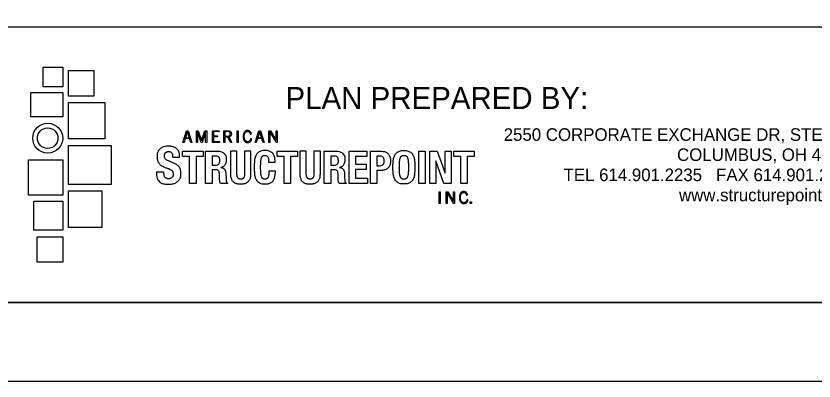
# Model space of a CAD drawing. Extents: x 10.6 to 44.6, y -2.6 to 23.4.
# Drawn here: x 13.5 to 18.57, y 1.43 to 3.75 of the extents above; entities that cross this region are included whole.
import ezdxf

# ---------------------------------------------------------------- set-up
doc = ezdxf.new("R2010")
doc.units = 0
for name, color, linetype in [('SH_Border', 7, 'Continuous'), ('SH_Cut_Line', 7, 'Continuous'), ('SH_Data', 7, 'Continuous')]:
    doc.layers.add(name, color=color, linetype=linetype)

msp = doc.modelspace()

# ---------------------------------------------------------------- linework, layer by layer
at = {"layer": 'SH_Border'}
msp.add_lwpolyline([(12.6028, 22.9265), (44.1028, 22.9265), (44.1028, 1.9265), (12.6028, 1.9265)], close=True, dxfattribs=at)
at = {"layer": 'SH_Cut_Line'}
msp.add_lwpolyline([(10.6028, 1.4265), (44.6028, 1.4265), (44.6028, 23.4265), (10.6028, 23.4265)], close=True, dxfattribs=at)
at = {"layer": 'SH_Data'}
for points in [[(13.2278, 1.9265), (19.2278, 1.9265), (19.2278, 3.6765), (13.2278, 3.6765)], [(13.6718, 3.4231), (13.7965, 3.4231), (13.7965, 3.2984), (13.6718, 3.2984)], [(13.8329, 3.4009), (13.995, 3.4009), (13.995, 3.2388), (13.8329, 3.2388)], [(13.5937, 3.2607), (13.7965, 3.2607), (13.7965, 3.1078), (13.5937, 3.1078)], [(13.8329, 3.1981), (14.0649, 3.1981), (14.0649, 2.9661), (13.8329, 2.9661)], [(13.8329, 2.9255), (14.1051, 2.9255), (14.1051, 2.676), (13.8329, 2.676)], [(13.579, 2.8342), (13.7965, 2.8342), (13.7965, 2.6096), (13.579, 2.6096)], [(13.8329, 2.6354), (14.0455, 2.6354), (14.0455, 2.4034), (13.8329, 2.4034)], [(13.6124, 2.5698), (13.7965, 2.5698), (13.7965, 2.3858), (13.6124, 2.3858)], [(13.6344, 2.3446), (13.7965, 2.3446), (13.7965, 2.1825), (13.6344, 2.1825)]]:
    msp.add_lwpolyline(points, close=True, dxfattribs=at)
for points in [[(14.5604, 2.9443), (14.5842, 3.0187), (14.5946, 3.0187), (14.6181, 2.9443), (14.6109, 2.9443), (14.6034, 2.9686), (14.5753, 2.9686), (14.5676, 2.9443), (14.5604, 2.9443)], [(14.577, 2.9742), (14.6019, 2.9742), (14.5895, 3.0131), (14.5893, 3.0131), (14.577, 2.9742)], [(14.6465, 2.9443), (14.6465, 3.0187), (14.6585, 3.0187), (14.6791, 2.9556), (14.6793, 2.9556), (14.6999, 3.0187), (14.7119, 3.0187), (14.7119, 2.9443), (14.7051, 2.9443), (14.7051, 3.0131), (14.7049, 3.0131), (14.6825, 2.9443), (14.676, 2.9443), (14.6536, 3.0131), (14.6533, 3.0131), (14.6533, 2.9443), (14.6465, 2.9443)], [(14.7478, 2.9443), (14.7478, 3.0187), (14.7903, 3.0187), (14.7903, 3.0131), (14.7546, 3.0131), (14.7546, 2.9858), (14.7803, 2.9858), (14.7803, 2.9802), (14.7546, 2.9802), (14.7546, 2.9499), (14.7923, 2.9499), (14.7923, 2.9443), (14.7478, 2.9443)], [(14.8532, 2.9795), (14.8715, 2.9443), (14.864, 2.9443), (14.8467, 2.9783), (14.8274, 2.9783), (14.8274, 2.9443), (14.8206, 2.9443), (14.8206, 3.0187), (14.8458, 3.0187)], [(14.8274, 3.0131), (14.8274, 2.9839), (14.8458, 2.9839)], [(14.8458, 3.0131), (14.8274, 3.0131)], [(14.9055, 3.0187), (14.9123, 3.0187), (14.9123, 2.9443), (14.9055, 2.9443), (14.9055, 3.0187)], [(15.0197, 2.9443), (15.0435, 3.0187), (15.0539, 3.0187), (15.0774, 2.9443), (15.0702, 2.9443), (15.0626, 2.9686), (15.0345, 2.9686), (15.0269, 2.9443), (15.0197, 2.9443)], [(15.0362, 2.9742), (15.0611, 2.9742), (15.0487, 3.0131), (15.0485, 3.0131), (15.0362, 2.9742)], [(15.1058, 3.0187), (15.1172, 3.0187), (15.1527, 2.9566), (15.1529, 2.9566), (15.1529, 3.0187), (15.1597, 3.0187), (15.1597, 2.9443), (15.1526, 2.9443), (15.1128, 3.0131), (15.1126, 3.0131), (15.1126, 2.9443), (15.1058, 2.9443), (15.1058, 3.0187)], [(14.6885, 2.8879), (14.6885, 2.8541), (14.6439, 2.8541), (14.6439, 2.6837), (14.6028, 2.6837), (14.6028, 2.8541), (14.5582, 2.8541), (14.5582, 2.8879), (14.6885, 2.8879)], [(14.7049, 2.6837), (14.7049, 2.8879), (14.7812, 2.8879)], [(14.746, 2.8574), (14.746, 2.7987), (14.7633, 2.7987)], [(14.7657, 2.8574), (14.746, 2.8574)], [(15.29, 2.8879), (15.29, 2.8541), (15.2453, 2.8541), (15.2453, 2.6837), (15.2043, 2.6837), (15.2043, 2.8541), (15.1596, 2.8541), (15.1596, 2.8879), (15.29, 2.8879)], [(15.459, 2.6837), (15.459, 2.8879), (15.5352, 2.8879)], [(15.5, 2.8574), (15.5, 2.7987), (15.5174, 2.7987)], [(15.5197, 2.8574), (15.5, 2.8574)], [(15.7307, 2.8879), (15.7307, 2.8541), (15.6577, 2.8541), (15.6577, 2.8064), (15.7264, 2.8064), (15.7264, 2.7725), (15.6577, 2.7725), (15.6577, 2.7176), (15.7336, 2.7176), (15.7336, 2.6837), (15.6167, 2.6837), (15.6167, 2.8879), (15.7307, 2.8879)], [(15.753, 2.6837), (15.753, 2.8879), (15.8249, 2.8879)], [(15.794, 2.8574), (15.794, 2.7959), (15.8123, 2.7959)], [(15.8112, 2.8574), (15.794, 2.8574)], [(16.0597, 2.6837), (16.0597, 2.8879), (16.1008, 2.8879), (16.1008, 2.6837), (16.0597, 2.6837)], [(16.1777, 2.8879), (16.2275, 2.7481), (16.2281, 2.7481), (16.2281, 2.8879), (16.2658, 2.8879), (16.2658, 2.6837), (16.2188, 2.6837), (16.1684, 2.8267), (16.1679, 2.8267), (16.1679, 2.6837), (16.1303, 2.6837), (16.1303, 2.8879), (16.1777, 2.8879)], [(16.4127, 2.8879), (16.4127, 2.8541), (16.3681, 2.8541), (16.3681, 2.6837), (16.327, 2.6837), (16.327, 2.8541), (16.2824, 2.8541), (16.2824, 2.8879), (16.4127, 2.8879)], [(14.7683, 2.7701), (14.746, 2.7701), (14.746, 2.6837), (14.7049, 2.6837)], [(14.7941, 2.7052), (14.793, 2.7444)], [(14.8018, 2.785), (14.8018, 2.7844)], [(15.5223, 2.7701), (15.5, 2.7701), (15.5, 2.6837), (15.459, 2.6837)], [(15.5482, 2.7052), (15.547, 2.7444)], [(15.5558, 2.785), (15.5558, 2.7844)], [(15.816, 2.7653), (15.794, 2.7653), (15.794, 2.6837), (15.753, 2.6837)], [(14.8439, 2.6854), (14.8439, 2.6837), (14.7993, 2.6837)], [(15.5979, 2.6854), (15.5979, 2.6837), (15.5533, 2.6837)], [(16.1901, 2.6307), (16.1969, 2.6307), (16.1969, 2.5562), (16.1901, 2.5562), (16.1901, 2.6307)], [(16.2335, 2.6307), (16.245, 2.6307), (16.2804, 2.5686), (16.2807, 2.5686), (16.2807, 2.6307), (16.2875, 2.6307), (16.2875, 2.5562), (16.2804, 2.5562), (16.2405, 2.6251), (16.2403, 2.6251), (16.2403, 2.5562), (16.2335, 2.5562), (16.2335, 2.6307)], [(16.386, 2.5562), (16.386, 2.5655), (16.3948, 2.5655), (16.3948, 2.5562), (16.386, 2.5562)]]:
    msp.add_lwpolyline(points, dxfattribs=at)
for radius in [0.0954, 0.0654]:
    msp.add_circle((13.7011, 2.9713), radius, dxfattribs=at)
for points in [[(14.8458, 3.0187), (14.8531, 3.0187), (14.8588, 3.0169), (14.8627, 3.0132), (14.8667, 3.0095), (14.8687, 3.0046), (14.8687, 2.9985), (14.8687, 2.9935), (14.8674, 2.9895), (14.865, 2.9863), (14.8625, 2.9832), (14.8586, 2.9809), (14.8532, 2.9795)], [(14.8458, 2.9839), (14.8507, 2.9839), (14.8546, 2.9852), (14.8575, 2.9877), (14.8604, 2.9903), (14.8619, 2.9939), (14.8619, 2.9985), (14.8619, 3.0031), (14.8605, 3.0067), (14.8578, 3.0092), (14.8552, 3.0118), (14.8511, 3.0131), (14.8458, 3.0131)], [(14.9897, 2.9968), (14.9881, 3.0023), (14.9858, 3.0065), (14.9829, 3.0095), (14.9799, 3.0125), (14.9761, 3.014), (14.9716, 3.014), (14.9679, 3.014), (14.9647, 3.0132), (14.962, 3.0115), (14.9594, 3.0098), (14.9572, 3.0075), (14.9554, 3.0046), (14.9537, 3.0016), (14.9524, 2.9982), (14.9516, 2.9942), (14.9508, 2.9902), (14.9503, 2.9859), (14.9503, 2.9814), (14.9503, 2.9769), (14.9508, 2.9726), (14.9516, 2.9687), (14.9524, 2.9647), (14.9537, 2.9612), (14.9555, 2.9583), (14.9573, 2.9553), (14.9596, 2.953), (14.9623, 2.9513), (14.9651, 2.9496), (14.9684, 2.9488), (14.9723, 2.9488), (14.9752, 2.9488), (14.9778, 2.9493), (14.9799, 2.9503), (14.982, 2.9513), (14.9837, 2.9526), (14.9852, 2.9543), (14.9866, 2.9559), (14.9878, 2.9578), (14.9887, 2.96), (14.9897, 2.9622), (14.9904, 2.9645), (14.991, 2.9669), (14.991, 2.9669), (14.9974, 2.9658), (14.9974, 2.9658), (14.9967, 2.9625), (14.9958, 2.9595), (14.9945, 2.9567), (14.9932, 2.9539), (14.9916, 2.9515), (14.9896, 2.9495), (14.9876, 2.9475), (14.9852, 2.946), (14.9823, 2.9449), (14.9795, 2.9438), (14.9761, 2.9432), (14.9722, 2.9432), (14.9677, 2.9432), (14.9636, 2.9441), (14.9601, 2.9459), (14.9565, 2.9477), (14.9535, 2.9503), (14.9511, 2.9537), (14.9487, 2.9571), (14.9468, 2.9611), (14.9455, 2.9658), (14.9442, 2.9704), (14.9435, 2.9757), (14.9435, 2.9814), (14.9435, 2.9872), (14.9442, 2.9924), (14.9455, 2.9971), (14.9468, 3.0018), (14.9487, 3.0058), (14.9511, 3.0091), (14.9535, 3.0125), (14.9565, 3.0151), (14.9601, 3.0169), (14.9636, 3.0187), (14.9677, 3.0197), (14.9722, 3.0197), (14.9755, 3.0197), (14.9784, 3.0191), (14.981, 3.018), (14.9837, 3.0169), (14.9859, 3.0154), (14.9879, 3.0135), (14.9899, 3.0116), (14.9915, 3.0093), (14.9928, 3.0067), (14.9941, 3.004), (14.9952, 3.0012), (14.996, 2.9982), (14.996, 2.9982), (14.9897, 2.9968), (14.9897, 2.9968)], [(14.4402, 2.7558), (14.4402, 2.7558), (14.4402, 2.749), (14.4402, 2.749), (14.4402, 2.7436), (14.4406, 2.7387), (14.4415, 2.7342), (14.4423, 2.7298), (14.4439, 2.7261), (14.4463, 2.723), (14.4487, 2.72), (14.4518, 2.7176), (14.4557, 2.7159), (14.4596, 2.7142), (14.4647, 2.7133), (14.471, 2.7133), (14.4781, 2.7133), (14.4845, 2.7156), (14.4903, 2.7203), (14.496, 2.725), (14.4988, 2.7322), (14.4988, 2.7419), (14.4988, 2.7471), (14.4981, 2.7516), (14.4967, 2.7554), (14.4953, 2.7592), (14.493, 2.7626), (14.4898, 2.7656), (14.4865, 2.7686), (14.4823, 2.7714), (14.477, 2.7739), (14.4717, 2.7764), (14.4651, 2.7789), (14.4574, 2.7815), (14.447, 2.785), (14.438, 2.7888), (14.4305, 2.7931), (14.4229, 2.7973), (14.4166, 2.8021), (14.4115, 2.8075), (14.4064, 2.8129), (14.4027, 2.8192), (14.4003, 2.8264), (14.3979, 2.8335), (14.3967, 2.8419), (14.3967, 2.8517), (14.3967, 2.8744), (14.4031, 2.8915), (14.4159, 2.9029), (14.4286, 2.9142), (14.4461, 2.9199), (14.4683, 2.9199), (14.4787, 2.9199), (14.4882, 2.9188), (14.497, 2.9165), (14.5057, 2.9142), (14.5133, 2.9106), (14.5196, 2.9055), (14.526, 2.9004), (14.531, 2.8939), (14.5345, 2.886), (14.5381, 2.8781), (14.5399, 2.8687), (14.5399, 2.8577), (14.5399, 2.8577), (14.5399, 2.8512), (14.5399, 2.8512), (14.5399, 2.8512), (14.495, 2.8512), (14.495, 2.8512), (14.495, 2.8622), (14.4931, 2.8707), (14.4892, 2.8766), (14.4854, 2.8826), (14.4789, 2.8856), (14.4699, 2.8856), (14.4648, 2.8856), (14.4605, 2.8848), (14.457, 2.8833), (14.4536, 2.8818), (14.4508, 2.8798), (14.4488, 2.8773), (14.4468, 2.8748), (14.4454, 2.8719), (14.4446, 2.8687), (14.4439, 2.8654), (14.4435, 2.8621), (14.4435, 2.8586), (14.4435, 2.8515), (14.445, 2.8454), (14.448, 2.8406), (14.4511, 2.8357), (14.4575, 2.8312), (14.4675, 2.8271), (14.4675, 2.8271), (14.5034, 2.8115), (14.5034, 2.8115), (14.5121, 2.8076), (14.5193, 2.8035), (14.525, 2.7993), (14.5307, 2.7951), (14.5352, 2.7905), (14.5386, 2.7857), (14.5419, 2.7808), (14.5443, 2.7754), (14.5456, 2.7696), (14.5469, 2.7637), (14.5475, 2.7572), (14.5475, 2.7501), (14.5475, 2.7256), (14.5404, 2.7077), (14.5263, 2.6962), (14.5121, 2.6847), (14.4924, 2.679), (14.4671, 2.679), (14.4407, 2.679), (14.4218, 2.6849), (14.4104, 2.6966), (14.3991, 2.7084), (14.3934, 2.725), (14.3934, 2.7464), (14.3934, 2.7464), (14.3934, 2.7558), (14.3934, 2.7558), (14.3934, 2.7558), (14.4402, 2.7558), (14.4402, 2.7558)], [(15.1054, 2.819), (15.1054, 2.8339), (15.1036, 2.8448), (15.1001, 2.8515), (15.0966, 2.8583), (15.0901, 2.8617), (15.0807, 2.8617), (15.0755, 2.8617), (15.0713, 2.8603), (15.0679, 2.8576), (15.0646, 2.8548), (15.0619, 2.8503), (15.06, 2.8442), (15.0581, 2.838), (15.0568, 2.8299), (15.056, 2.8199), (15.0552, 2.8099), (15.0548, 2.7977), (15.0548, 2.7832), (15.0548, 2.7678), (15.0554, 2.7554), (15.0564, 2.7458), (15.0575, 2.7363), (15.0591, 2.729), (15.0613, 2.7237), (15.0635, 2.7185), (15.0663, 2.715), (15.0697, 2.7132), (15.0731, 2.7114), (15.0769, 2.7104), (15.0814, 2.7104), (15.085, 2.7104), (15.0884, 2.7111), (15.0916, 2.7123), (15.0948, 2.7135), (15.0975, 2.716), (15.0998, 2.7198), (15.1021, 2.7235), (15.104, 2.7287), (15.1053, 2.7355), (15.1066, 2.7423), (15.1073, 2.7512), (15.1073, 2.7623), (15.1073, 2.7623), (15.1484, 2.7623), (15.1484, 2.7623), (15.1484, 2.7512), (15.1475, 2.7407), (15.1458, 2.7308), (15.1441, 2.7209), (15.1409, 2.7121), (15.1362, 2.7045), (15.1315, 2.697), (15.1249, 2.691), (15.1164, 2.6865), (15.1079, 2.6821), (15.0969, 2.6799), (15.0834, 2.6799), (15.0679, 2.6799), (15.0556, 2.6825), (15.0464, 2.6878), (15.0373, 2.693), (15.0303, 2.7003), (15.0254, 2.7097), (15.0205, 2.719), (15.0174, 2.7302), (15.016, 2.7433), (15.0145, 2.7564), (15.0138, 2.7706), (15.0138, 2.7861), (15.0138, 2.8015), (15.0145, 2.8158), (15.016, 2.8289), (15.0174, 2.8419), (15.0205, 2.8531), (15.0254, 2.8625), (15.0302, 2.8718), (15.0372, 2.8791), (15.0464, 2.8844), (15.0555, 2.8896), (15.0678, 2.8922), (15.0833, 2.8922), (15.0979, 2.8922), (15.1095, 2.8898), (15.118, 2.885), (15.1265, 2.8802), (15.1328, 2.8741), (15.137, 2.8668), (15.1412, 2.8594), (15.1438, 2.8514), (15.1449, 2.8429), (15.1459, 2.8345), (15.1464, 2.8265), (15.1464, 2.819), (15.1464, 2.819), (15.1054, 2.819), (15.1054, 2.819)], [(15.8958, 2.7861), (15.8958, 2.8015), (15.8965, 2.8158), (15.8979, 2.8289), (15.8994, 2.8419), (15.9025, 2.8531), (15.9074, 2.8625), (15.9123, 2.8718), (15.9193, 2.8791), (15.9285, 2.8844), (15.9376, 2.8896), (15.95, 2.8922), (15.9655, 2.8922), (15.9809, 2.8922), (15.9933, 2.8896), (16.0024, 2.8844), (16.0116, 2.8791), (16.0186, 2.8718), (16.0235, 2.8625), (16.0284, 2.8531), (16.0315, 2.8419), (16.033, 2.8289), (16.0344, 2.8158), (16.0351, 2.8015), (16.0351, 2.7861), (16.0351, 2.7776), (16.0349, 2.7695), (16.0345, 2.7618)], [(14.7633, 2.7987), (14.7734, 2.7987), (14.7811, 2.801), (14.7865, 2.8057), (14.7919, 2.8104), (14.7946, 2.8182), (14.7946, 2.8292), (14.7946, 2.848), (14.785, 2.8574), (14.7657, 2.8574)], [(14.7812, 2.8879), (14.7982, 2.8879), (14.8115, 2.8836), (14.8212, 2.8748), (14.8308, 2.866), (14.8357, 2.8529), (14.8357, 2.8353), (14.8357, 2.8216), (14.8329, 2.8104), (14.8274, 2.8017), (14.8219, 2.793), (14.8133, 2.7875), (14.8018, 2.785)], [(14.9042, 2.8879), (14.9042, 2.8879), (14.9042, 2.7458), (14.9042, 2.7458), (14.9042, 2.7407), (14.9045, 2.736), (14.9052, 2.7317), (14.9058, 2.7274), (14.9071, 2.7237), (14.9089, 2.7206), (14.9107, 2.7174), (14.9132, 2.715), (14.9164, 2.7132), (14.9195, 2.7114), (14.9235, 2.7104), (14.9283, 2.7104), (14.933, 2.7104), (14.937, 2.7114), (14.9402, 2.7132), (14.9433, 2.715), (14.9458, 2.7174), (14.9476, 2.7206), (14.9494, 2.7237), (14.9507, 2.7274), (14.9514, 2.7317), (14.952, 2.736), (14.9524, 2.7407), (14.9524, 2.7458), (14.9524, 2.7458), (14.9524, 2.8879), (14.9524, 2.8879), (14.9524, 2.8879), (14.9934, 2.8879), (14.9934, 2.8879), (14.9934, 2.8879), (14.9934, 2.7456), (14.9934, 2.7456), (14.9934, 2.7327), (14.9916, 2.722), (14.988, 2.7135), (14.9843, 2.705), (14.9795, 2.6983), (14.9734, 2.6933), (14.9673, 2.6884), (14.9604, 2.6849), (14.9525, 2.6829), (14.9447, 2.6809), (14.9366, 2.6799), (14.9283, 2.6799), (14.9199, 2.6799), (14.9118, 2.6808), (14.904, 2.6825), (14.8962, 2.6842), (14.8892, 2.6875), (14.8831, 2.6923), (14.877, 2.6972), (14.8722, 2.7039), (14.8686, 2.7123), (14.8649, 2.7208), (14.8631, 2.7319), (14.8631, 2.7456), (14.8631, 2.7456), (14.8631, 2.8879), (14.8631, 2.8879), (14.8631, 2.8879), (14.9042, 2.8879), (14.9042, 2.8879)], [(15.345, 2.8879), (15.345, 2.8879), (15.345, 2.7458), (15.345, 2.7458), (15.345, 2.7407), (15.3453, 2.736), (15.346, 2.7317), (15.3467, 2.7274), (15.3479, 2.7237), (15.3497, 2.7206), (15.3516, 2.7174), (15.354, 2.715), (15.3572, 2.7132), (15.3604, 2.7114), (15.3643, 2.7104), (15.3691, 2.7104), (15.3739, 2.7104), (15.3779, 2.7114), (15.381, 2.7132), (15.3842, 2.715), (15.3867, 2.7174), (15.3885, 2.7206), (15.3903, 2.7237), (15.3915, 2.7274), (15.3922, 2.7317), (15.3929, 2.736), (15.3932, 2.7407), (15.3932, 2.7458), (15.3932, 2.7458), (15.3932, 2.8879), (15.3932, 2.8879), (15.3932, 2.8879), (15.4342, 2.8879), (15.4342, 2.8879), (15.4342, 2.8879), (15.4342, 2.7456), (15.4342, 2.7456), (15.4342, 2.7327), (15.4324, 2.722), (15.4288, 2.7135), (15.4252, 2.705), (15.4203, 2.6983), (15.4143, 2.6933), (15.4081, 2.6884), (15.4012, 2.6849), (15.3934, 2.6829), (15.3856, 2.6809), (15.3775, 2.6799), (15.3691, 2.6799), (15.3607, 2.6799), (15.3526, 2.6808), (15.3448, 2.6825), (15.337, 2.6842), (15.3301, 2.6875), (15.324, 2.6923), (15.3179, 2.6972), (15.313, 2.7039), (15.3094, 2.7123), (15.3058, 2.7208), (15.304, 2.7319), (15.304, 2.7456), (15.304, 2.7456), (15.304, 2.8879), (15.304, 2.8879), (15.304, 2.8879), (15.345, 2.8879), (15.345, 2.8879)], [(15.5174, 2.7987), (15.5274, 2.7987), (15.5351, 2.801), (15.5405, 2.8057), (15.5459, 2.8104), (15.5487, 2.8182), (15.5487, 2.8292), (15.5487, 2.848), (15.539, 2.8574), (15.5197, 2.8574)], [(15.5352, 2.8879), (15.5522, 2.8879), (15.5656, 2.8836), (15.5752, 2.8748), (15.5849, 2.866), (15.5897, 2.8529), (15.5897, 2.8353), (15.5897, 2.8216), (15.5869, 2.8104), (15.5814, 2.8017), (15.5759, 2.793), (15.5674, 2.7875), (15.5558, 2.785)], [(15.8123, 2.7959), (15.8205, 2.7959), (15.8271, 2.7983), (15.8322, 2.8032), (15.8373, 2.8082), (15.8398, 2.8158), (15.8398, 2.8262), (15.8398, 2.8362), (15.8376, 2.8439), (15.8332, 2.8493), (15.8288, 2.8547), (15.8215, 2.8574), (15.8112, 2.8574)], [(15.8249, 2.8879), (15.8353, 2.8879), (15.8441, 2.8862), (15.8513, 2.8827), (15.8584, 2.8791), (15.8642, 2.8745), (15.8685, 2.8688), (15.8729, 2.8631), (15.8761, 2.8566), (15.878, 2.8492), (15.8799, 2.8419), (15.8808, 2.8344), (15.8808, 2.8268), (15.8808, 2.8161), (15.8792, 2.8069), (15.8761, 2.7992), (15.873, 2.7915), (15.8686, 2.7851), (15.863, 2.7802), (15.8573, 2.7752), (15.8505, 2.7715), (15.8425, 2.769), (15.8345, 2.7666), (15.8257, 2.7653), (15.816, 2.7653)], [(15.9368, 2.7861), (15.9368, 2.7724), (15.9372, 2.7607), (15.9378, 2.7511), (15.9385, 2.7415), (15.9399, 2.7337), (15.9419, 2.7277), (15.9439, 2.7217), (15.9468, 2.7174), (15.9506, 2.7146), (15.9543, 2.7118), (15.9593, 2.7104), (15.9655, 2.7104), (15.9716, 2.7104), (15.9766, 2.7118), (15.9803, 2.7146), (15.9841, 2.7174), (15.987, 2.7217), (15.989, 2.7277), (15.991, 2.7337), (15.9924, 2.7415), (15.9931, 2.7511), (15.9937, 2.7607), (15.9941, 2.7724), (15.9941, 2.7861), (15.9941, 2.7998), (15.9937, 2.8114), (15.9931, 2.8209), (15.9924, 2.8304), (15.991, 2.8382), (15.989, 2.8443), (15.987, 2.8504), (15.9841, 2.8548), (15.9803, 2.8576), (15.9766, 2.8603), (15.9716, 2.8617), (15.9655, 2.8617), (15.9593, 2.8617), (15.9543, 2.8603), (15.9506, 2.8576), (15.9468, 2.8548), (15.9439, 2.8504), (15.9419, 2.8443), (15.9399, 2.8382), (15.9385, 2.8304), (15.9378, 2.8209), (15.9372, 2.8114), (15.9368, 2.7998), (15.9368, 2.7861)], [(14.793, 2.7444), (14.7926, 2.7524), (14.7905, 2.7587), (14.7867, 2.7632), (14.783, 2.7678), (14.7768, 2.7701), (14.7683, 2.7701)], [(14.8018, 2.7844), (14.8088, 2.7835), (14.8144, 2.7817), (14.8186, 2.7791), (14.8229, 2.7765), (14.8262, 2.7728), (14.8285, 2.768), (14.8309, 2.7631), (14.8325, 2.757), (14.8333, 2.7495), (14.834, 2.7421), (14.8345, 2.7329), (14.8347, 2.7221), (14.8349, 2.7112), (14.8355, 2.7029), (14.8366, 2.6972), (14.8376, 2.6914), (14.84, 2.6875), (14.8439, 2.6854)], [(15.547, 2.7444), (15.5466, 2.7524), (15.5445, 2.7587), (15.5408, 2.7632), (15.537, 2.7678), (15.5309, 2.7701), (15.5223, 2.7701)], [(15.5558, 2.7844), (15.5628, 2.7835), (15.5685, 2.7817), (15.5727, 2.7791), (15.5769, 2.7765), (15.5802, 2.7728), (15.5826, 2.768), (15.585, 2.7631), (15.5865, 2.757), (15.5873, 2.7495), (15.5881, 2.7421), (15.5885, 2.7329), (15.5887, 2.7221), (15.5889, 2.7112), (15.5895, 2.7029), (15.5906, 2.6972), (15.5916, 2.6914), (15.5941, 2.6875), (15.5979, 2.6854)], [(16.0345, 2.7618), (16.0341, 2.7554), (16.0336, 2.7492), (16.033, 2.7433), (16.0315, 2.7302), (16.0284, 2.719), (16.0235, 2.7097), (16.0186, 2.7003), (16.0116, 2.693), (16.0024, 2.6878), (15.9933, 2.6825), (15.9809, 2.6799), (15.9655, 2.6799), (15.95, 2.6799), (15.9376, 2.6825), (15.9285, 2.6878), (15.9193, 2.693), (15.9123, 2.7003), (15.9074, 2.7097), (15.9025, 2.719), (15.8994, 2.7302), (15.8979, 2.7433), (15.8965, 2.7564), (15.8958, 2.7706), (15.8958, 2.7861)], [(14.7993, 2.6837), (14.7972, 2.6866), (14.7959, 2.6899), (14.7953, 2.6936), (14.7947, 2.6973), (14.7943, 2.7012), (14.7941, 2.7052)], [(15.5533, 2.6837), (15.5512, 2.6866), (15.5499, 2.6899), (15.5493, 2.6936), (15.5487, 2.6973), (15.5484, 2.7012), (15.5482, 2.7052)], [(16.3642, 2.6088), (16.3626, 2.6143), (16.3603, 2.6185), (16.3574, 2.6215), (16.3544, 2.6245), (16.3506, 2.626), (16.3461, 2.626), (16.3424, 2.626), (16.3392, 2.6252), (16.3365, 2.6235), (16.3339, 2.6218), (16.3317, 2.6195), (16.3299, 2.6165), (16.3282, 2.6136), (16.3269, 2.6101), (16.3261, 2.6062), (16.3252, 2.6022), (16.3248, 2.5979), (16.3248, 2.5934), (16.3248, 2.5889), (16.3252, 2.5846), (16.3261, 2.5806), (16.3269, 2.5766), (16.3282, 2.5732), (16.33, 2.5702), (16.3318, 2.5673), (16.3341, 2.565), (16.3368, 2.5633), (16.3396, 2.5616), (16.3429, 2.5608), (16.3468, 2.5608), (16.3497, 2.5608), (16.3523, 2.5613), (16.3544, 2.5623), (16.3565, 2.5633), (16.3582, 2.5646), (16.3597, 2.5662), (16.3611, 2.5679), (16.3623, 2.5698), (16.3632, 2.572), (16.3642, 2.5742), (16.3649, 2.5765), (16.3655, 2.5789), (16.3655, 2.5789), (16.3719, 2.5778), (16.3719, 2.5778), (16.3712, 2.5745), (16.3703, 2.5714), (16.369, 2.5686), (16.3677, 2.5659), (16.3661, 2.5635), (16.3641, 2.5615), (16.3621, 2.5595), (16.3597, 2.5579), (16.3568, 2.5568), (16.354, 2.5557), (16.3506, 2.5552), (16.3467, 2.5552), (16.3421, 2.5552), (16.3381, 2.5561), (16.3346, 2.5579), (16.331, 2.5597), (16.328, 2.5623), (16.3256, 2.5657), (16.3232, 2.569), (16.3213, 2.5731), (16.32, 2.5777), (16.3187, 2.5824), (16.318, 2.5876), (16.318, 2.5934), (16.318, 2.5992), (16.3187, 2.6044), (16.32, 2.6091), (16.3213, 2.6137), (16.3232, 2.6177), (16.3256, 2.6211), (16.328, 2.6245), (16.331, 2.6271), (16.3346, 2.6289), (16.3381, 2.6307), (16.3421, 2.6316), (16.3467, 2.6316), (16.35, 2.6316), (16.3529, 2.6311), (16.3555, 2.63), (16.3582, 2.6289), (16.3604, 2.6274), (16.3624, 2.6255), (16.3644, 2.6235), (16.366, 2.6213), (16.3673, 2.6186), (16.3686, 2.616), (16.3697, 2.6132), (16.3705, 2.6101), (16.3705, 2.6101), (16.3642, 2.6088), (16.3642, 2.6088)]]:
    msp.add_open_spline(points, degree=3, dxfattribs=at)

# ---------------------------------------------------------------- texts
for s, height, p in [('PLAN PREPARED BY:', 0.14, (15.2126, 3.1568)), ('2550 CORPORATE EXCHANGE DR, STE 300', 0.08, (16.5999, 2.9542)), ('COLUMBUS, OH 43231', 0.08, (17.7019, 2.8261)), ('TEL 614.901.2235   FAX 614.901.2236', 0.08, (16.9805, 2.6979)), ('www.structurepoint.com', 0.08, (17.7141, 2.5697))]:
    msp.add_text(s, height=height, dxfattribs=at).set_placement(p)

doc.saveas('drawing.dxf')
